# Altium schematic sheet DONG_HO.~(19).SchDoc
size A
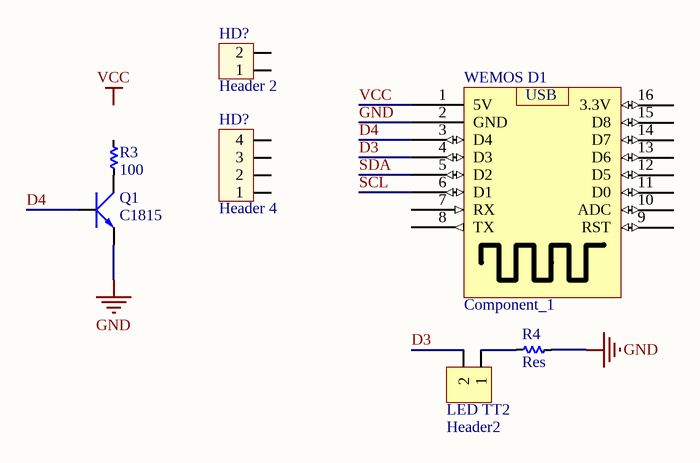
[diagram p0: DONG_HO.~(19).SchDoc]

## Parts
(Parts that share a designator on the sheet are numbered #1, #2 ... from top to bottom, then left to right.)
HD?#1  Header 2  [HED2]
HD?#2  Header 4  [HED4]
LED_TT2  Header2  [Header2]
Q1  C1815  [QTO-92]
R3  100  [RES-1/8W-SMALL]
R4  Res  [RES-1/8W-SMALL]
WEMOS_D1  Component_1  [ESP WEMOS MINI]

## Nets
GND: Q1.1(E) R4.2 WEMOS_D1.2(GND)
VCC: WEMOS_D1.1(5V)
D3: LED_TT2.2 WEMOS_D1.4(D3)
D4: Q1.3(B) WEMOS_D1.3(D4)
SCL: WEMOS_D1.6(D1)
SDA: WEMOS_D1.5(D2)
NetLED_TT2_1: LED_TT2.1 R4.1
NetQ1_2: Q1.2(C) R3.1

Not connected (* = marked no-connect by the designer): HD?#1 1 2; HD?#2 1 2 3 4; R3 2; WEMOS_D1 7(RX) 8(TX) 9(RST) 10(ADC) 11(D0) 12(D5) 13(D6) 14(D7) 15(D8) 16(3.3V)

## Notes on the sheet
- Labels drawn without touching a wire or pin: VCC

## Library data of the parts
HD?#1 = Hed2: Header 2 (Green)
HD?#2 = Hed4: Header 4 (Green)
LED_TT2 = Header2: Header IDC, 2 x 1 Pin Vertical 2.54mm Pitch (Non-Boxed, Male); Manufacturer: W¨¹rth Elektronik eiSos GmbH; partNo: 613002143121; ComponentLink1 Description: Manufacturer; ComponentLink2 Description: Datasheet; NoPins: 02
Q1 = C1815: NPN 600mW, ECB
R3 R4 = Res: Manufacturer: Generic Components; Class: Passive; SubClass: R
